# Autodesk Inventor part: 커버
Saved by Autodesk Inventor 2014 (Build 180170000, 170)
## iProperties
Created: 2024-05
Part Number: 커버
Material: 일반
Document SubType Name: Modeling
Designer: dg
Density: 1 g/cm^3
Appearance: 기본값
Author: dg
Author: jhkim
Creation Date: 2024-05-07
Sending System: Autodesk Inventor 2025
Preprocessor: ST-DEVELOPER v20
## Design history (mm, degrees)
node "커버1"
node "솔리드1"
node "기준1"
